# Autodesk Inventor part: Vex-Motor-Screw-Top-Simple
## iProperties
Created: 2007-08
Part Number: Vex-Motor-Screw-Top-Simple
Material: Steel, Mild
Document SubType Name: Modeling
Density: 7.86 g/cm^3
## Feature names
1. Base1
